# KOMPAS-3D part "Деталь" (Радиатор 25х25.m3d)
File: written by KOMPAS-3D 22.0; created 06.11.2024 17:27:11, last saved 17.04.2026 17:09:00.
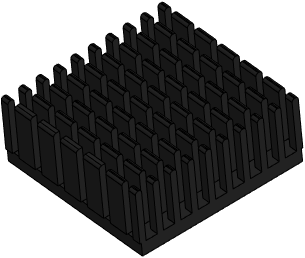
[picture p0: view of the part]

Document properties: Автор: Andrey; Полное имя файла: C:\Users\User1\Documents\Работа\Корпуса\Корпус Repka Pi 5\Конструкторская документация\3д модель\Repka_5_3D\Радиатор 25х25.m3d

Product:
- Part/product: Деталь
    Масса: 0.020327

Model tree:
1. Эскиз:1
2. Элемент выдавливания:1
     Расстояние 1 = 2
3. Эскиз:2  (with: Элемент выдавливания:1)
4. Элемент выдавливания:2
     Расстояние 1 = 8
5. Эскиз:3  (with: Элемент выдавливания:2)
6. Элемент выдавливания:3
     Расстояние 2 = 8
7. Скругление:1  (with: Элемент выдавливания:2)
     Радиус = 0.4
